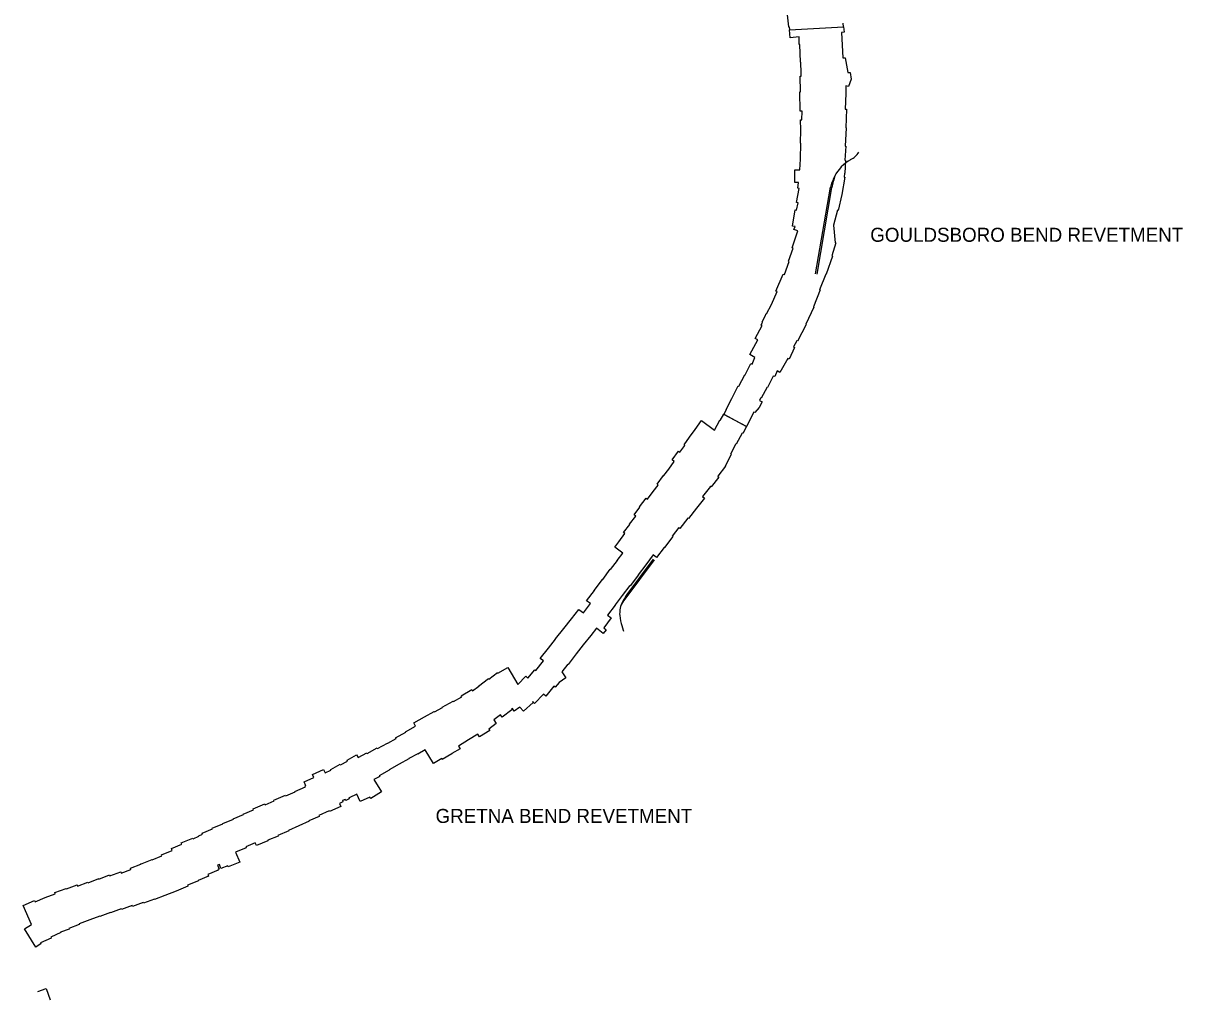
# Model space of a CAD drawing. Extents: x 2650582 to 3923188, y 277893 to 989177.
# Drawn here: x 3676552 to 3689765, y 514908 to 526041 of the extents above; entities that cross this region are included whole.
import ezdxf

# ---------------------------------------------------------------- set-up
doc = ezdxf.new("R2010")
doc.units = 0
doc.layers.add('Level 3', color=7, linetype='Continuous')

msp = doc.modelspace()

# ---------------------------------------------------------------- linework, layer by layer
at = {"layer": 'Level 3'}
for p, q in [((3685582, 523185), (3685750, 524171)), ((3685601, 523182), (3685768, 524169))]:
    msp.add_line(p, q, dxfattribs=at)
for points in [[(3685257, 526138), (3685273, 525999), (3685280, 526000), (3685283, 525967), (3685899, 526001), (3685894, 526043)], [(3685410, 525596), (3685400, 525797), (3685395, 525797), (3685393, 525886), (3685293, 525875), (3685283, 525967), (3685899, 526001)], [(3685899, 526001), (3685905, 525940), (3685878, 525937), (3685891, 525645), (3685919, 525646)], [(3685919, 525646), (3685950, 525479), (3685977, 525481), (3685987, 525405), (3685955, 525319), (3685927, 525327), (3685927, 525239), (3685925, 525239), (3685919, 525061), (3685935, 525061)], [(3685405, 525039), (3685403, 525258), (3685408, 525258), (3685404, 525437), (3685417, 525438), (3685417, 525471), (3685415, 525471), (3685414, 525597), (3685410, 525596)], [(3685364, 523911), (3685382, 523995), (3685365, 523999), (3685395, 524158), (3685379, 524161), (3685387, 524227), (3685346, 524227), (3685346, 524369), (3685401, 524369), (3685410, 524490), (3685408, 524491), (3685414, 524672), (3685408, 524673), (3685414, 524826), (3685408, 524939), (3685423, 524940), (3685427, 525039), (3685405, 525039)], [(3685935, 525061), (3685927, 524850), (3685931, 524849), (3685920, 524640), (3685927, 524639), (3685915, 524478), (3685923, 524477), (3685913, 524333), (3685910, 524333), (3685907, 524287), (3685913, 524285), (3685882, 524090), (3685879, 524090), (3685839, 523907), (3685832, 523908), (3685787, 523737)], [(3684832, 522265), (3684922, 522430), (3684893, 522445), (3684971, 522595), (3684960, 522600), (3684975, 522633), (3684971, 522636), (3685007, 522703), (3685019, 522730), (3685021, 522729), (3685077, 522834), (3685143, 522981), (3685127, 522988), (3685210, 523180), (3685227, 523175), (3685281, 523325), (3685273, 523329), (3685325, 523477), (3685316, 523481), (3685380, 523673), (3685335, 523688), (3685347, 523724), (3685319, 523727), (3685349, 523913), (3685364, 523911)], [(3685787, 523737), (3685804, 523539), (3685811, 523536), (3685766, 523388), (3685774, 523385), (3685702, 523180), (3685697, 523182), (3685626, 523002), (3685632, 523000), (3685556, 522807), (3685560, 522804), (3685469, 522610), (3685474, 522607), (3685374, 522417), (3685367, 522420), (3685330, 522351), (3685341, 522345), (3685279, 522210), (3685265, 522217), (3685174, 522060), (3685142, 522080)], [(3684795, 521445), (3684535, 521581), (3684566, 521637), (3684563, 521639), (3684628, 521763), (3684625, 521764), (3684700, 521906), (3684706, 521903), (3684775, 522034), (3684778, 522033), (3684845, 522161), (3684860, 522154), (3684890, 522231), (3684832, 522265)], [(3685142, 522080), (3685116, 522012), (3685098, 522018), (3685032, 521890), (3685028, 521893), (3684960, 521765), (3684955, 521768), (3684941, 521740), (3684973, 521723), (3684939, 521660), (3684887, 521603), (3684879, 521607), (3684795, 521445)], [(3683576, 520526), (3683651, 520625), (3683664, 520615), (3683730, 520702), (3683732, 520701), (3683788, 520776), (3683776, 520785), (3683850, 520884), (3683851, 520884), (3683908, 520959), (3683907, 520959), (3683971, 521044), (3683946, 521062), (3684019, 521162), (3684035, 521150), (3684091, 521226), (3684082, 521233), (3684146, 521321), (3684144, 521322), (3684208, 521410), (3684208, 521411), (3684280, 521511), (3684430, 521402), (3684490, 521514), (3684495, 521511), (3684535, 521585)], [(3684535, 521585), (3684795, 521445), (3684752, 521365), (3684744, 521369), (3684677, 521243), (3684673, 521245), (3684610, 521128), (3684620, 521123), (3684550, 520993), (3684553, 520991), (3684466, 520876), (3684468, 520875), (3684467, 520873), (3684478, 520865), (3684393, 520754), (3684383, 520762), (3684381, 520760), (3684382, 520760), (3684294, 520644), (3684315, 520628), (3684224, 520513), (3684226, 520512), (3684132, 520393), (3684126, 520397), (3684035, 520282), (3684022, 520292)], [(3682885, 519358), (3682937, 519318), (3683017, 519424), (3682972, 519457), (3683061, 519574), (3683059, 519575), (3683154, 519700), (3683155, 519700), (3683242, 519816), (3683245, 519814), (3683323, 519916), (3683322, 519917), (3683385, 520001), (3683295, 520069), (3683340, 520129), (3683339, 520129), (3683409, 520223), (3683393, 520235), (3683463, 520328), (3683462, 520329), (3683532, 520423), (3683512, 520438), (3683577, 520525), (3683576, 520526)], [(3684022, 520292), (3683947, 520193), (3683954, 520188), (3683860, 520064), (3683856, 520066), (3683769, 519950), (3683731, 519979), (3683647, 519868), (3683647, 519868), (3683561, 519754), (3683562, 519753), (3683467, 519628), (3683465, 519630), (3683379, 519516), (3683378, 519516), (3683297, 519409), (3683298, 519408), (3683211, 519294), (3683253, 519262), (3683167, 519148), (3683193, 519127), (3683162, 519085), (3683084, 519143)], [(3683732, 519930), (3683430, 519527), (3683415, 519506), (3683402, 519484), (3683388, 519459), (3683373, 519428), (3683359, 519390), (3683354, 519372), (3683351, 519353), (3683350, 519337), (3683349, 519323), (3683348, 519309), (3683350, 519290), (3683354, 519259), (3683360, 519228), (3683365, 519199), (3683372, 519174), (3683381, 519148), (3683389, 519122), (3683393, 519110)], [(3683742, 519923), (3683406, 519474), (3683394, 519458), (3683381, 519438), (3683369, 519418)], [(3682187, 518502), (3682279, 518596), (3682302, 518573), (3682383, 518671), (3682394, 518662), (3682479, 518771), (3682443, 518799), (3682536, 518918), (3682537, 518917), (3682619, 519021), (3682618, 519022), (3682711, 519141), (3682713, 519139), (3682800, 519251), (3682801, 519250), (3682885, 519358)], [(3683084, 519143), (3683020, 519061), (3683019, 519062), (3682934, 518954), (3682933, 518955), (3682852, 518852), (3682853, 518851), (3682760, 518732), (3682758, 518733), (3682690, 518646), (3682736, 518579), (3682660, 518527), (3682614, 518472), (3682600, 518485), (3682506, 518371), (3682481, 518392), (3682377, 518287), (3682356, 518308), (3682364, 518299), (3682252, 518199), (3682210, 518245)], [(3679752, 517391), (3679862, 517443), (3679847, 517476), (3679974, 517535), (3679992, 517496), (3680059, 517527), (3680056, 517533), (3680164, 517593), (3680169, 517585), (3680248, 517629), (3680243, 517639), (3680351, 517699), (3680368, 517669), (3680466, 517723), (3680470, 517715), (3680584, 517779), (3680588, 517771), (3680704, 517835), (3680706, 517832), (3680801, 517885), (3680796, 517895), (3680912, 517959), (3680910, 517962), (3681024, 518026), (3681003, 518065), (3681125, 518133), (3681126, 518132), (3681235, 518193), (3681237, 518189), (3681331, 518241), (3681328, 518245), (3681450, 518313), (3681454, 518307), (3681551, 518361), (3681543, 518375), (3681663, 518447), (3681673, 518429), (3681744, 518482), (3681741, 518485), (3681853, 518570), (3681857, 518564), (3681957, 518639), (3681962, 518632), (3682075, 518697), (3682187, 518502)], [(3682210, 518245), (3682148, 518199), (3682126, 518228), (3682116, 518221), (3682121, 518214), (3682009, 518130), (3681990, 518155), (3681913, 518099), (3681943, 518057), (3681858, 517995), (3681868, 517978), (3681751, 517907), (3681734, 517935), (3681627, 517870), (3681627, 517870), (3681512, 517800), (3681530, 517770), (3681435, 517714), (3681437, 517711), (3681328, 517647), (3681322, 517657), (3681227, 517601)], [(3681227, 517601), (3681134, 517757), (3681049, 517710), (3681048, 517713), (3680946, 517657), (3680948, 517655), (3680837, 517594), (3680838, 517593), (3680722, 517528), (3680724, 517525), (3680610, 517462), (3680614, 517455), (3680547, 517418), (3680634, 517280), (3680513, 517203), (3680503, 517218), (3680390, 517169), (3680354, 517251), (3680265, 517212), (3680263, 517211), (3680268, 517198), (3680229, 517180), (3680222, 517193), (3680189, 517179), (3680196, 517165), (3680155, 517146), (3680171, 517113), (3680044, 517054), (3680040, 517061)], [(3678127, 516561), (3678250, 516611), (3678241, 516633), (3678359, 516682), (3678353, 516696), (3678485, 516751), (3678488, 516744), (3678554, 516772), (3678552, 516778), (3678595, 516796), (3678591, 516807), (3678709, 516856), (3678706, 516864), (3678826, 516913), (3678826, 516916), (3678948, 516966), (3678946, 516972), (3679063, 517020), (3679060, 517025), (3679178, 517074), (3679173, 517086), (3679306, 517141), (3679310, 517131), (3679413, 517176), (3679409, 517185), (3679541, 517242), (3679545, 517232), (3679650, 517278), (3679648, 517282), (3679770, 517335), (3679765, 517346), (3679772, 517349), (3679752, 517391)], [(3680040, 517061), (3679922, 517010), (3679926, 516999), (3679808, 516948), (3679810, 516943), (3679692, 516892), (3679693, 516890), (3679577, 516839), (3679578, 516836), (3679454, 516782), (3679457, 516775), (3679339, 516727), (3679341, 516720), (3679209, 516666), (3679196, 516698), (3679089, 516653), (3679094, 516640), (3678973, 516590), (3679020, 516477), (3678888, 516423), (3678882, 516437), (3678805, 516405), (3678787, 516449), (3678768, 516441), (3678785, 516399), (3678771, 516393), (3678774, 516385), (3678657, 516336), (3678665, 516316), (3678547, 516267), (3678548, 516265), (3678425, 516214), (3678429, 516203), (3678297, 516148)], [(3678297, 516148), (3678297, 516148), (3678166, 516096), (3678165, 516098), (3678048, 516052), (3678047, 516056), (3677923, 516009), (3677920, 516016), (3677797, 515970), (3677792, 515984), (3677672, 515939), (3677670, 515946), (3677547, 515900), (3677545, 515904), (3677424, 515859), (3677424, 515860), (3677310, 515819), (3677311, 515818), (3677189, 515774), (3677191, 515766), (3677071, 515722), (3677074, 515714), (3676978, 515679), (3676980, 515674), (3676866, 515623), (3676872, 515610), (3676751, 515557), (3676757, 515548), (3676696, 515509), (3676566, 515716), (3676648, 515768), (3676552, 515983), (3676681, 516041), (3676688, 516025), (3676801, 516075), (3676802, 516073), (3676916, 516115), (3676911, 516130), (3677042, 516177), (3677044, 516173), (3677166, 516217), (3677170, 516205), (3677290, 516249), (3677292, 516243), (3677414, 516289), (3677415, 516285), (3677536, 516331), (3677540, 516322), (3677663, 516368), (3677669, 516351), (3677780, 516392), (3677774, 516409), (3677891, 516453), (3677890, 516456), (3678021, 516507), (3678022, 516505), (3678132, 516548), (3678127, 516561)], [(3676720, 515001), (3676814, 515036), (3676860, 514908)]]:
    msp.add_lwpolyline(points, dxfattribs=at)
for centre, radius, start, end in [((3686204, 524088), 456, 119.411, 153.1836), ((3685870, 524703), 244, 296.9528, 327.3525), ((3686224, 524056), 488, 150.9149, 166.3771), ((3686585, 524028), 829, 160.387, 170.2308)]:
    msp.add_arc(centre, radius, start, end, dxfattribs=at)

# ---------------------------------------------------------------- texts
for s, p in [('GOULDSBORO BEND REVETMENT', (3686204, 523549)), ('GRETNA BEND REVETMENT', (3681251, 516924))]:
    msp.add_text(s, height=160, dxfattribs=at).set_placement(p)

doc.saveas('drawing.dxf')
